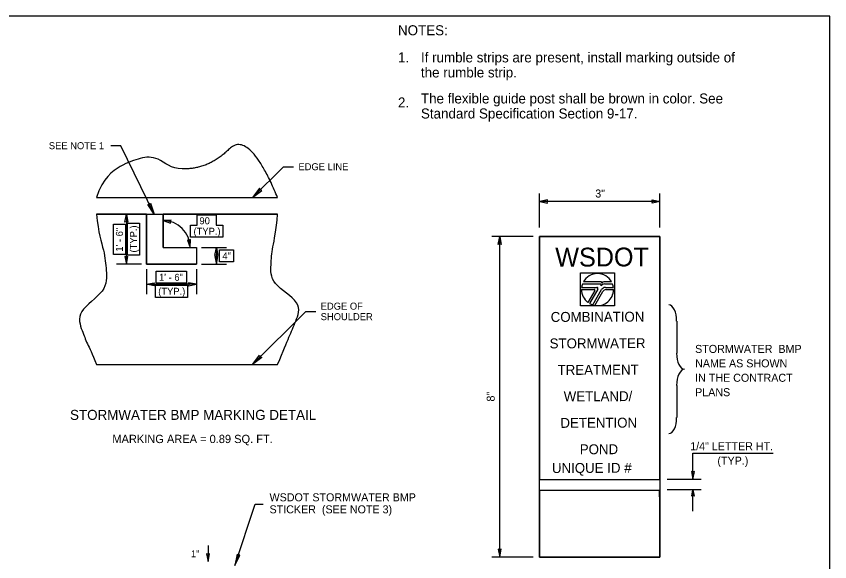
# Model space of a CAD drawing. Extents: x 99862 to 103151, y 100000 to 102076.
# Drawn here: x 101526 to 103151, y 100986 to 102076 of the extents above; entities that cross this region are included whole.
import ezdxf

# ---------------------------------------------------------------- set-up
doc = ezdxf.new("R2010")
doc.units = 0
for name, color, linetype in [('Default', 7, 'Continuous'), ('Level 1', 7, 'Continuous'), ('Level 15', 7, 'Continuous'), ('Level 17', 7, 'Continuous'), ('Level 2', 7, 'Continuous'), ('Level 20', 7, 'Continuous'), ('Level 60', 7, 'Continuous'), ('SH_DE_DetailBody1Text', 7, 'Continuous'), ('SH_DE_DetailHeading1Text', 7, 'Continuous'), ('SH_DE_DetailHeading2Text', 7, 'Continuous'), ('SH_DE_DetailLevel1', 7, 'Continuous'), ('SH_DE_DetailLevel9', 7, 'Continuous'), ('SH_GI_GeneralNotesBodyText', 7, 'Continuous'), ('SH_GI_WSDOTLogo', 7, 'Continuous')]:
    doc.layers.add(name, color=color, linetype=linetype)

msp = doc.modelspace()

# ---------------------------------------------------------------- linework, layer by layer
at = {"layer": 'Default'}
for points in [[(102653.2, 101563.1), (102720.8, 101563.1), (102720.8, 101497.4), (102653.2, 101497.4)], [(102570.8, 101150.8), (102811.3, 101150.8), (102811.3, 101128.7), (102570.8, 101128.7)]]:
    msp.add_lwpolyline(points, close=True, dxfattribs=at)
at = {"layer": 'Level 1'}
msp.add_lwpolyline([(99862, 99999.5), (103151, 99999.5), (103151, 102075.5), (99862, 102075.5)], close=True, dxfattribs=at)
at = {"layer": 'Level 15'}
for p, q in [((101734.6, 101817.1), (101714.6, 101817.1)), ((102059.4, 101775.1), (102079.4, 101775.1)), ((102571.3, 101653.6), (102571.3, 101721.6)), ((102811.7, 101653.6), (102811.7, 101721.6)), ((102558.6, 101635.6), (102475.7, 101635.6)), ((102811.3, 101635.6), (102571.3, 101635.6)), ((102571.3, 101635.6), (102571.3, 101150.8)), ((102811.3, 101150.8), (102811.3, 101635.6)), ((101895.7, 101613.6), (101945.7, 101613.6)), ((101775.7, 101580.3), (101725.7, 101580.3)), ((101785.7, 101570.3), (101785.7, 101520.3)), ((101885.7, 101570.3), (101885.7, 101520.3)), ((101895.7, 101580.3), (101945.7, 101580.3)), ((102103.9, 101486.2), (102123.9, 101486.2)), ((102845.2, 101466.9), (102845.2, 101402.7)), ((102845.2, 101338.5), (102845.2, 101274.3)), ((102877.8, 101203.2), (103037.8, 101203.2)), ((102571.3, 101150.8), (102811.3, 101150.8)), ((102893.8, 101150.8), (102826.2, 101150.8)), ((102893.8, 101130.2), (102826.2, 101130.2)), ((102811.1, 101128.7), (102571.1, 101128.7)), ((102571.1, 101128.7), (102571.3, 100995.6)), ((102811.3, 101102.7), (102811.1, 101128.7)), ((102003, 101101.1), (102019, 101101.1)), ((102811.3, 100995.6), (102811.3, 101102.7)), ((102558.6, 100995.6), (102475.7, 100995.6)), ((102571.3, 100995.6), (102811.3, 100995.6))]:
    msp.add_line(p, q, dxfattribs=at)
for points in [[(101997.9, 101713.6), (102016, 101727.8), (102013.1, 101729.2), (102011.7, 101732)], [(101801.3, 101680.1), (101788.7, 101699.4), (101791.9, 101699.8), (101794.1, 101702)], [(102571.7, 101705.6), (102587.4, 101702.5), (102586.7, 101705.6), (102587.4, 101708.7)], [(102812.2, 101705.6), (102796.4, 101702.5), (102797.2, 101705.6), (102796.4, 101708.7)], [(101745.7, 101680.3), (101748.7, 101664.5), (101745.7, 101665.3), (101742.6, 101664.5)], [(102491.7, 101635.6), (102494.8, 101619.8), (102491.7, 101620.6), (102488.6, 101619.8)], [(101925.7, 101613.6), (101928.7, 101597.9), (101925.7, 101598.6), (101922.6, 101597.9)], [(101745.7, 101580.3), (101748.7, 101596), (101745.7, 101595.3), (101742.6, 101596)], [(101925.7, 101580.3), (101928.7, 101596), (101925.7, 101595.3), (101922.6, 101596)], [(101785.7, 101540.3), (101801.4, 101543.3), (101800.7, 101540.3), (101801.4, 101537.2)], [(101885.7, 101540.3), (101869.9, 101543.3), (101870.7, 101540.3), (101869.9, 101537.2)], [(101997.9, 101380.3), (102011.9, 101398.5), (102013.3, 101395.7), (102016.1, 101394.3)], [(102877.8, 101150.8), (102880.8, 101166.6), (102877.8, 101165.8), (102874.7, 101166.6)], [(102877.8, 101130.2), (102880.2, 101117.6), (102877.8, 101118.2), (102875.3, 101117.6)], [(101962.5, 100979.1), (101972.4, 100999.8), (101969.3, 100999.8), (101966.8, 101001.7)], [(102491.7, 100995.6), (102494.8, 101011.3), (102491.7, 101010.6), (102488.6, 101011.3)]]:
    msp.add_lwpolyline(points, close=True, dxfattribs=at)
for points in [[(102812.2, 101705.6), (102571.7, 101705.6)], [(102491.7, 100995.6), (102491.7, 101635.6)], [(102653.2, 101563.1), (102720.8, 101563.1), (102720.8, 101497.4), (102653.2, 101497.4), (102653.2, 101563.1)], [(102811.3, 101150.8), (102811.3, 101150.8)]]:
    msp.add_lwpolyline(points, dxfattribs=at)
for centre, major_axis, start_param, end_param in [((102829.7, 101466.9), (0, 32.1), 4.712389, 6.283196), ((102860.6, 101402.7), (0, -32.1), 4.712389, 6.283196), ((102860.6, 101338.5), (0, 32.1), 6.283174, 7.853982), ((102829.7, 101274.3), (0, -32.1), 6.283174, 7.853982)]:
    msp.add_ellipse(centre, major_axis=major_axis, ratio=0.481891, start_param=start_param, end_param=end_param, dxfattribs=at)
at = {"layer": 'Level 17'}
for p, q in [((102571.3, 100995.6), (102571.3, 101635.6)), ((102571.3, 101635.6), (102811.3, 101635.6)), ((102811.3, 101635.6), (102811.3, 100995.6)), ((102811.3, 100995.6), (102571.3, 100995.6))]:
    msp.add_line(p, q, dxfattribs=at)
at = {"layer": 'Level 2'}
msp.add_line((102571.3, 100995.6), (102811.3, 100995.6), dxfattribs=at)
at = {"layer": 'Level 60'}
msp.add_line((103151, 102075.5), (103151, 102075.5), dxfattribs=at)
at = {"layer": 'SH_DE_DetailLevel1'}
for p, q in [((101685.7, 101713.6), (102047.9, 101713.6)), ((101685.7, 101713.6), (102047.9, 101713.6)), ((101685.7, 101680.3), (102047.9, 101680.3)), ((101785.7, 101580.3), (101785.7, 101680.3)), ((101785.7, 101680.3), (101785.7, 101580.3)), ((102047.9, 101680.3), (101819, 101680.3)), ((101819, 101680.3), (101819, 101613.6)), ((101819, 101613.6), (101819, 101680.3)), ((101887.2, 101674.2), (101887.2, 101679.2)), ((101887.2, 101658.2), (101887.2, 101674.2)), ((101925.2, 101674.2), (101925.2, 101658.2)), ((101719.7, 101655.6), (101719.7, 101660.6)), ((101747.7, 101657.3), (101747.7, 101662.3)), ((101747.7, 101662.3), (101752.7, 101662.3)), ((101771.7, 101662.3), (101771.7, 101657.3)), ((101874.1, 101653.2), (101874.1, 101658.2)), ((101925.2, 101658.2), (101933.2, 101658.2)), ((101879.1, 101634.2), (101874.1, 101634.2)), ((101819, 101613.6), (101885.7, 101613.6)), ((101819, 101613.6), (101885.7, 101613.6)), ((101885.7, 101613.6), (101885.7, 101580.3)), ((101885.7, 101613.6), (101885.7, 101580.3)), ((101936.4, 101608.9), (101954.9, 101608.9)), ((101954.9, 101608.9), (101959.9, 101608.9)), ((101959.9, 101608.9), (101959.9, 101603.9)), ((101743.7, 101599.9), (101738.7, 101599.9)), ((101936.4, 101584.9), (101931.4, 101584.9)), ((101885.7, 101580.3), (101785.7, 101580.3)), ((101785.7, 101580.3), (101885.7, 101580.3)), ((101810.3, 101566.3), (101861.1, 101566.3)), ((101861.1, 101566.3), (101866.1, 101566.3)), ((101803.6, 101538.3), (101808.6, 101538.3)), ((101810.3, 101542.3), (101805.3, 101542.3)), ((101808.6, 101538.3), (101862.7, 101538.3)), ((101862.7, 101538.3), (101867.7, 101538.3)), ((101867.7, 101538.3), (101867.7, 101533.3)), ((101867.7, 101533.3), (101867.7, 101519.3)), ((101867.7, 101519.3), (101867.7, 101514.3)), ((101685.7, 101380.3), (102047.9, 101380.3)), ((101685.7, 101380.3), (102047.9, 101380.3))]:
    msp.add_line(p, q, dxfattribs=at)
for points in [[(101785.7, 101680.3), (101745.7, 101680.3), (101685.7, 101680.3)], [(101887.2, 101679.2), (101892.2, 101679.2), (101920.2, 101679.2)], [(101920.2, 101679.2), (101925.2, 101679.2), (101925.2, 101674.2)], [(101719.7, 101660.6), (101724.7, 101660.6), (101738.7, 101660.6)], [(101719.7, 101599.9), (101719.7, 101604.9), (101719.7, 101655.6)], [(101738.7, 101660.6), (101743.7, 101660.6), (101743.7, 101655.6)], [(101743.7, 101655.6), (101743.7, 101604.9), (101743.7, 101599.9)], [(101747.7, 101598.2), (101747.7, 101603.2), (101747.7, 101657.3)], [(101752.7, 101662.3), (101766.7, 101662.3), (101771.7, 101662.3)], [(101771.7, 101657.3), (101771.7, 101603.2), (101771.7, 101598.2)], [(101874.1, 101658.2), (101879.1, 101658.2), (101887.2, 101658.2)], [(101874.1, 101634.2), (101874.1, 101639.2), (101874.1, 101653.2)], [(101933.2, 101658.2), (101938.2, 101658.2), (101938.2, 101653.2)], [(101938.2, 101653.2), (101938.2, 101639.2), (101938.2, 101634.2)], [(101938.2, 101634.2), (101933.2, 101634.2), (101879.1, 101634.2)], [(101931.4, 101603.9), (101931.4, 101608.9), (101936.4, 101608.9)], [(101931.4, 101584.9), (101931.4, 101589.9), (101931.4, 101603.9)], [(101959.9, 101603.9), (101959.9, 101589.9), (101959.9, 101584.9)], [(101738.7, 101599.9), (101724.7, 101599.9), (101719.7, 101599.9)], [(101771.7, 101598.2), (101766.7, 101598.2), (101752.7, 101598.2), (101747.7, 101598.2)], [(101959.9, 101584.9), (101954.9, 101584.9), (101936.4, 101584.9)], [(101805.3, 101561.3), (101805.3, 101566.3), (101810.3, 101566.3)], [(101805.3, 101542.3), (101805.3, 101547.3), (101805.3, 101561.3)], [(101866.1, 101566.3), (101866.1, 101561.3), (101866.1, 101547.3), (101866.1, 101542.3)], [(101803.6, 101514.3), (101803.6, 101519.3), (101803.6, 101533.3), (101803.6, 101538.3)], [(101866.1, 101542.3), (101861.1, 101542.3), (101810.3, 101542.3)], [(101867.7, 101514.3), (101862.7, 101514.3), (101808.6, 101514.3), (101803.6, 101514.3)]]:
    msp.add_lwpolyline(points, dxfattribs=at)
for points, degree in [([(102047.9, 101713.6), (101990.6, 101850.6), (101910.6, 101769.6), (101857, 101770.8)], 2), ([(101857, 101770.8), (101836.1, 101770.6), (101807.7, 101797.2), (101774.2, 101793.1), (101736.2, 101779.8), (101698.7, 101753), (101685.7, 101713.6)], 3), ([(101685.7, 101680.3), (101689.5, 101643.1), (101702.5, 101605), (101705.3, 101568.9), (101708.5, 101526.6), (101643.2, 101485.9), (101658.3, 101445.1), (101666.3, 101423.4), (101677.4, 101402.2), (101685.7, 101380.3)], 3), ([(102047.9, 101380.3), (102059.7, 101408.5), (102071.5, 101436.8), (102083.3, 101465.1), (102099.3, 101503.6), (102032.4, 101541.7), (102034.7, 101580.6), (102036.6, 101611.7), (102045.4, 101647), (102047.9, 101680.3)], 3)]:
    msp.add_open_spline(points, degree=degree, dxfattribs=at)
at = {"layer": 'SH_DE_DetailLevel9'}
for p, q in [((101801.4, 101680.3), (101734.6, 101817.1)), ((101997.9, 101713.6), (102059.4, 101775.1)), ((101745.7, 101680.3), (101745.7, 101630.3)), ((101745.7, 101580.3), (101745.7, 101630.3)), ((101925.7, 101613.6), (101925.7, 101596.9)), ((101925.7, 101580.3), (101925.7, 101596.9)), ((101785.7, 101540.3), (101835.7, 101540.3)), ((101885.7, 101540.3), (101835.7, 101540.3)), ((101997.9, 101380.3), (102103.9, 101486.2)), ((102877.8, 101150.8), (102877.8, 101203.2)), ((102877.8, 101087.4), (102877.8, 101130.2)), ((101962.5, 100979.1), (102003, 101101.1)), ((101908.8, 101018.5), (101908.8, 100986.6))]:
    msp.add_line(p, q, dxfattribs=at)
for points in [[(101835, 101668.6), (101819, 101667.8), (101834.1, 101662.5), (101833.9, 101665.7)], [(101867.9, 101628.7), (101873.2, 101613.6), (101874, 101629.6), (101871.1, 101628.4)], [(101908.8, 100986.6), (101911.9, 101002.3), (101908.8, 101001.6), (101905.7, 101002.3)]]:
    msp.add_lwpolyline(points, close=True, dxfattribs=at)
msp.add_arc((101819, 101613.6), 54.2, 0, 90, dxfattribs=at)
at = {"layer": 'SH_GI_WSDOTLogo'}
for p, q in [((102692.2, 101540.9), (102657, 101540.9)), ((102694.3, 101545.1), (102658.9, 101545.1)), ((102715.1, 101545.1), (102699.5, 101545.1)), ((102717, 101540.9), (102700.7, 101540.9)), ((102700.7, 101540.9), (102700.7, 101540.9)), ((102655, 101529.8), (102680.2, 101529.8)), ((102655.3, 101534), (102685.8, 101534)), ((102681.4, 101527.8), (102667.7, 101504.3)), ((102687.6, 101530.8), (102670.9, 101502.2)), ((102677.7, 101499.2), (102695.3, 101529.7)), ((102681.8, 101498.3), (102697.7, 101525.9)), ((102702.8, 101534), (102718.7, 101534)), ((102704.3, 101529.7), (102719, 101529.7))]:
    msp.add_line(p, q, dxfattribs=at)
for centre, radius, start, end in [((102687, 101529.8), 32, 28.4787, 151.532), ((102687, 101529.8), 32, 159.696, 172.5057), ((102692.2, 101538.5), 2.36, 327.8418, 89.9985), ((102700.7, 101533.2), 7.74, 89.9953, 147.8238), ((102694.3, 101543.6), 1.44, 329.8742, 90.0033), ((102699.5, 101540.5), 4.59, 90.0072, 148.1676), ((102687, 101529.8), 32, 7.4943, 20.2941), ((102687, 101529.8), 32, 179.9986, 232.8433), ((102680.2, 101528.5), 1.31, 329.7436, 90), ((102687, 101529.8), 32, 260.5455, 359.8086), ((102685.8, 101531.9), 2.1, 329.7683, 90), ((102702.8, 101525.3), 8.66, 90, 149.9974), ((102704.3, 101522.1), 7.61, 90, 150.0543), ((102687, 101529.8), 32, 239.7929, 253.0448)]:
    msp.add_arc(centre, radius, start, end, dxfattribs=at)

# ---------------------------------------------------------------- texts
at = {"layer": 'Level 20'}
for s, height, p in [('NOTES:', 20, (102288.3, 102037.6)), ('1.', 20, (102288.3, 101983.4)), ('If rumble strips are present, install marking outside of ', 20, (102334.2, 101983.4)), ('the rumble strip.', 20, (102334.2, 101953.4)), ('2.', 20, (102288.3, 101893.4)), ('The flexible guide post shall be brown in color. See', 20, (102334.2, 101901.4)), ('Standard Specification Section 9-17.', 20, (102334.2, 101871.4)), ('SEE NOTE 1', 14, (101590.8, 101810.1)), ('EDGE LINE', 14, (102089.4, 101768.1)), ('3"', 16, (102682.5, 101713.6)), ('EDGE OF', 14, (102133.9, 101489.7)), ('SHOULDER', 14, (102133.9, 101468.7)), ('STORMWATER  BMP', 16, (102882, 101403.3)), ('NAME AS SHOWN ', 16, (102882, 101374.5)), ('IN THE CONTRACT ', 16, (102882, 101345.7)), ('PLANS', 16, (102882, 101316.9)), ('1/4" LETTER HT.', 16, (102872.2, 101209)), ('(TYP.)', 16, (102926.6, 101180.2)), ('WSDOT STORMWATER BMP', 16, (102031.7, 101107)), ('STICKER  (SEE NOTE 3)', 16, (102031.7, 101083))]:
    msp.add_text(s, height=height, dxfattribs=at).set_placement(p)
msp.add_text('8"', height=16, rotation=90, dxfattribs=at).set_placement((102481.6, 101306.2))
at = {"layer": 'SH_DE_DetailBody1Text'}
for s, p in [('90', (101891.7, 101660.2)), ('(TYP.)', (101879.8, 101639.2)), ('4"', (101937.5, 101589.9)), ('1\' - 6"', (101810.9, 101547.3)), ('(TYP.)', (101809.3, 101519.3))]:
    msp.add_text(s, height=14, dxfattribs=at).set_placement(p)
for s, p in [('1\' - 6"', (101738.7, 101605.5)), ('(TYP.)', (101766.7, 101603.8))]:
    msp.add_text(s, height=14, rotation=90, dxfattribs=at).set_placement(p)
at = {"layer": 'SH_DE_DetailHeading1Text'}
msp.add_text('STORMWATER BMP MARKING DETAIL', height=20, dxfattribs=at).set_placement((101633.1, 101269.6))
at = {"layer": 'SH_DE_DetailHeading2Text'}
msp.add_text('MARKING AREA = 0.89 SQ. FT. ', height=16.5, dxfattribs=at).set_placement((101717.6, 101223.3))
at = {"layer": 'SH_DE_DetailLevel9'}
msp.add_text('1"', height=13.67, dxfattribs=at).set_placement((101874.8, 100995.4))
at = {"layer": 'SH_GI_GeneralNotesBodyText'}
for s, height, p in [('WSDOT', 37.57, (102602.7, 101575.6)), ('COMBINATION', 19.832, (102593.5, 101465.2)), ('STORMWATER', 19.83, (102591.4, 101412.3)), ('TREATMENT', 19.83, (102607.3, 101359.4)), ('WETLAND/', 19.83, (102619.5, 101306.6)), ('DETENTION', 19.83, (102612.9, 101253.7)), ('POND', 19.83, (102651.6, 101200.9)), ('UNIQUE ID #', 19.832, (102596, 101163.5))]:
    msp.add_text(s, height=height, rotation=0.188, dxfattribs=at).set_placement(p)

doc.saveas('drawing.dxf')
